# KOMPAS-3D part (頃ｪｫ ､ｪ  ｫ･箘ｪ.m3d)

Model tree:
1. Эскиз:1
2. Операция выдавливания:1
     Расстояние 1 = 10
3. Эскиз:2
4. Вырезать элемент выдавливания:1
     Угол 2 = 1.91; Расстояние 1 = 7
5. Эскиз:3
6. Вырезать элемент выдавливания:2
     Угол 2 = 1.91; Расстояние 1 = 1
7. Эскиз:4
8. Вырезать элемент выдавливания:3
     Угол 2 = 1.91; Расстояние 1 = 2
9. Эскиз:5
10. Вырезать элемент выдавливания:4
     Расстояние 2 = 62.5; Расстояние 1 = 62.5
11. Эскиз:6
12. Операция выдавливания:2
     Расстояние 1 = 62.5; Расстояние 2 = 62.5
13. Эскиз:7
14. Вырезать элемент выдавливания:5
     Расстояние 2 = 59; Расстояние 1 = 59
15. Скругление:1
     Радиус = 0.5
16. Скругление:2
     Радиус = 0.5
17. Эскиз:8
18. Вырезать элемент выдавливания:6
     Расстояние 2 = 62.5; Расстояние 1 = 62.5
